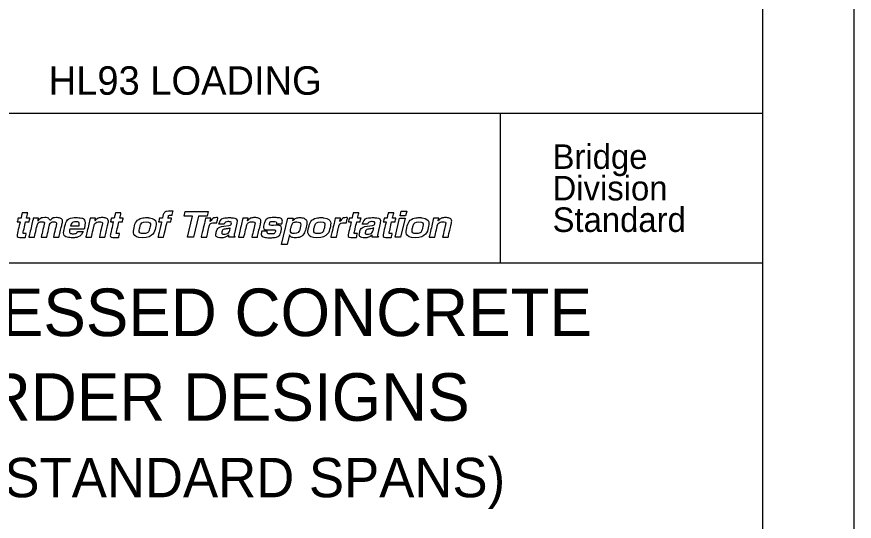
# Model space of a CAD drawing. Extents: x 998.6 to 1033.3, y 1000 to 1011.
# Drawn here: x 1014.706 to 1017, y 1001.382 to 1002.765 of the extents above; entities that cross this region are included whole.
import ezdxf

# ---------------------------------------------------------------- set-up
doc = ezdxf.new("R2010")
doc.units = 0
for name, color, linetype in [('D_BATCH_PLOT', 7, 'Continuous'), ('D_SHEET', 7, 'Continuous'), ('Working Level 1', 7, 'Continuous')]:
    doc.layers.add(name, color=color, linetype=linetype)

msp = doc.modelspace()

# ---------------------------------------------------------------- linework, layer by layer
at = {"layer": 'D_BATCH_PLOT'}
msp.add_lwpolyline([(1000, 1000), (1017, 1000), (1017, 1011), (1000, 1011)], close=True, dxfattribs=at)
at = {"layer": 'D_SHEET'}
for p, q in [((1017, 1000), (1017, 1011)), ((1016.75, 1000.25), (1016.75, 1010.75)), ((1013.725, 1002.5), (1016.75, 1002.5)), ((1016.0306, 1002.09), (1016.0306, 1002.5)), ((1015.1642, 1002.2186), (1015.1672, 1002.2311)), ((1015.1672, 1002.2311), (1015.2304, 1002.2311)), ((1015.2304, 1002.2311), (1015.2274, 1002.2186)), ((1015.756, 1002.219), (1015.759, 1002.2317)), ((1015.759, 1002.2317), (1015.7742, 1002.2317)), ((1015.7742, 1002.2317), (1015.7712, 1002.219)), ((1015.1877, 1002.2186), (1015.1642, 1002.2186)), ((1015.1741, 1002.1604), (1015.1877, 1002.2186)), ((1015.204, 1002.2186), (1015.1904, 1002.1604)), ((1015.2274, 1002.2186), (1015.204, 1002.2186)), ((1015.3088, 1002.199), (1015.3021, 1002.1707)), ((1015.7018, 1002.199), (1015.6952, 1002.1707)), ((1015.7424, 1002.1604), (1015.7546, 1002.2128)), ((1015.7546, 1002.2128), (1015.7697, 1002.2128)), ((1015.7712, 1002.219), (1015.756, 1002.219)), ((1015.7697, 1002.2128), (1015.7575, 1002.1604)), ((1014.8536, 1002.1918), (1014.8771, 1002.1918)), ((1014.8727, 1002.1758), (1014.8883, 1002.1758)), ((1015.2739, 1002.1958), (1015.2593, 1002.1958)), ((1015.2731, 1002.191), (1015.2872, 1002.1929)), ((1015.2893, 1002.1792), (1015.2909, 1002.1859)), ((1015.667, 1002.1958), (1015.6524, 1002.1958)), ((1015.6662, 1002.191), (1015.6803, 1002.1929)), ((1015.6824, 1002.1792), (1015.6839, 1002.1859)), ((1015.1904, 1002.1604), (1015.1741, 1002.1604)), ((1015.7575, 1002.1604), (1015.7424, 1002.1604)), ((1013.725, 1002.09), (1016.75, 1002.09))]:
    msp.add_line(p, q, dxfattribs=at)
for points in [[(1015.4533, 1002.1671), (1015.4531, 1002.1671), (1015.4468, 1002.1401), (1015.4316, 1002.1401), (1015.4486, 1002.2128), (1015.4631, 1002.2128), (1015.4614, 1002.2052), (1015.4616, 1002.2052)], [(1014.8912, 1002.1853), (1014.8906, 1002.1829), (1014.8511, 1002.1829)], [(1015.3036, 1002.1625), (1015.3031, 1002.1604), (1015.2868, 1002.1604)], [(1015.6966, 1002.1625), (1015.6962, 1002.1604), (1015.6798, 1002.1604)]]:
    msp.add_lwpolyline(points, dxfattribs=at)
for points, degree in [([(1014.7327, 1002.2128), (1014.7327, 1002.2128), (1014.7421, 1002.2128), (1014.7421, 1002.2128), (1014.7421, 1002.2128), (1014.7398, 1002.2029), (1014.7398, 1002.2029), (1014.7398, 1002.2029), (1014.7304, 1002.2029), (1014.7304, 1002.2029), (1014.7304, 1002.2029), (1014.7238, 1002.1745), (1014.7238, 1002.1745), (1014.7231, 1002.1714), (1014.7229, 1002.1703), (1014.7291, 1002.1703), (1014.73, 1002.1703), (1014.7312, 1002.1704), (1014.7323, 1002.1705), (1014.7323, 1002.1705), (1014.7298, 1002.16), (1014.7298, 1002.16), (1014.7274, 1002.1599), (1014.725, 1002.1598), (1014.7226, 1002.1598), (1014.7226, 1002.1598), (1014.7207, 1002.1598), (1014.7207, 1002.1598), (1014.7076, 1002.1598), (1014.7063, 1002.1644), (1014.7079, 1002.1712), (1014.7079, 1002.1712), (1014.7153, 1002.2029), (1014.7153, 1002.2029), (1014.7153, 1002.2029), (1014.7075, 1002.2029), (1014.7075, 1002.2029), (1014.7075, 1002.2029), (1014.7098, 1002.2128), (1014.7098, 1002.2128), (1014.7098, 1002.2128), (1014.7176, 1002.2128), (1014.7176, 1002.2128), (1014.7176, 1002.2128), (1014.7209, 1002.2269), (1014.7209, 1002.2269), (1014.7209, 1002.2269), (1014.736, 1002.2269), (1014.736, 1002.2269), (1014.736, 1002.2269), (1014.7327, 1002.2128), (1014.7327, 1002.2128)], 3), ([(1014.9882, 1002.2128), (1014.9882, 1002.2128), (1014.9976, 1002.2128), (1014.9976, 1002.2128), (1014.9976, 1002.2128), (1014.9953, 1002.2029), (1014.9953, 1002.2029), (1014.9953, 1002.2029), (1014.9859, 1002.2029), (1014.9859, 1002.2029), (1014.9859, 1002.2029), (1014.9792, 1002.1745), (1014.9792, 1002.1745), (1014.9785, 1002.1714), (1014.9783, 1002.1703), (1014.9845, 1002.1703), (1014.9855, 1002.1703), (1014.9866, 1002.1704), (1014.9877, 1002.1705), (1014.9877, 1002.1705), (1014.9853, 1002.16), (1014.9853, 1002.16), (1014.9829, 1002.1599), (1014.9804, 1002.1598), (1014.9781, 1002.1598), (1014.9781, 1002.1598), (1014.9761, 1002.1598), (1014.9761, 1002.1598), (1014.963, 1002.1598), (1014.9617, 1002.1644), (1014.9633, 1002.1712), (1014.9633, 1002.1712), (1014.9707, 1002.2029), (1014.9707, 1002.2029), (1014.9707, 1002.2029), (1014.9629, 1002.2029), (1014.9629, 1002.2029), (1014.9629, 1002.2029), (1014.9652, 1002.2128), (1014.9652, 1002.2128), (1014.9652, 1002.2128), (1014.973, 1002.2128), (1014.973, 1002.2128), (1014.973, 1002.2128), (1014.9763, 1002.2269), (1014.9763, 1002.2269), (1014.9763, 1002.2269), (1014.9915, 1002.2269), (1014.9915, 1002.2269), (1014.9915, 1002.2269), (1014.9882, 1002.2128), (1014.9882, 1002.2128)], 3), ([(1015.108, 1002.1604), (1015.108, 1002.1604), (1015.0929, 1002.1604), (1015.0929, 1002.1604), (1015.0929, 1002.1604), (1015.1028, 1002.2029), (1015.1028, 1002.2029), (1015.1028, 1002.2029), (1015.0945, 1002.2029), (1015.0945, 1002.2029), (1015.0945, 1002.2029), (1015.0968, 1002.2128), (1015.0968, 1002.2128), (1015.0968, 1002.2128), (1015.1051, 1002.2128), (1015.1051, 1002.2128), (1015.1051, 1002.2128), (1015.1061, 1002.217), (1015.1061, 1002.217), (1015.1086, 1002.2278), (1015.1161, 1002.2319), (1015.1265, 1002.2319), (1015.1309, 1002.2319), (1015.1329, 1002.2318), (1015.1342, 1002.2317), (1015.1342, 1002.2317), (1015.1316, 1002.2206), (1015.1316, 1002.2206), (1015.1316, 1002.2206), (1015.1274, 1002.2206), (1015.1274, 1002.2206), (1015.1222, 1002.2206), (1015.1218, 1002.2192), (1015.1207, 1002.2148), (1015.1207, 1002.2148), (1015.1203, 1002.2128), (1015.1203, 1002.2128), (1015.1203, 1002.2128), (1015.1301, 1002.2128), (1015.1301, 1002.2128), (1015.1301, 1002.2128), (1015.1278, 1002.2029), (1015.1278, 1002.2029), (1015.1278, 1002.2029), (1015.118, 1002.2029), (1015.118, 1002.2029), (1015.118, 1002.2029), (1015.108, 1002.1604), (1015.108, 1002.1604)], 3), ([(1015.6396, 1002.2128), (1015.6396, 1002.2128), (1015.649, 1002.2128), (1015.649, 1002.2128), (1015.649, 1002.2128), (1015.6467, 1002.2029), (1015.6467, 1002.2029), (1015.6467, 1002.2029), (1015.6373, 1002.2029), (1015.6373, 1002.2029), (1015.6373, 1002.2029), (1015.6306, 1002.1745), (1015.6306, 1002.1745), (1015.6299, 1002.1714), (1015.6298, 1002.1703), (1015.6359, 1002.1703), (1015.6369, 1002.1703), (1015.638, 1002.1704), (1015.6391, 1002.1705), (1015.6391, 1002.1705), (1015.6367, 1002.16), (1015.6367, 1002.16), (1015.6343, 1002.1599), (1015.6319, 1002.1598), (1015.6295, 1002.1598), (1015.6295, 1002.1598), (1015.6275, 1002.1598), (1015.6275, 1002.1598), (1015.6144, 1002.1598), (1015.6131, 1002.1644), (1015.6147, 1002.1712), (1015.6147, 1002.1712), (1015.6221, 1002.2029), (1015.6221, 1002.2029), (1015.6221, 1002.2029), (1015.6143, 1002.2029), (1015.6143, 1002.2029), (1015.6143, 1002.2029), (1015.6166, 1002.2128), (1015.6166, 1002.2128), (1015.6166, 1002.2128), (1015.6244, 1002.2128), (1015.6244, 1002.2128), (1015.6244, 1002.2128), (1015.6277, 1002.2269), (1015.6277, 1002.2269), (1015.6277, 1002.2269), (1015.6429, 1002.2269), (1015.6429, 1002.2269), (1015.6429, 1002.2269), (1015.6396, 1002.2128), (1015.6396, 1002.2128)], 3), ([(1015.7353, 1002.2128), (1015.7353, 1002.2128), (1015.7447, 1002.2128), (1015.7447, 1002.2128), (1015.7447, 1002.2128), (1015.7424, 1002.2029), (1015.7424, 1002.2029), (1015.7424, 1002.2029), (1015.733, 1002.2029), (1015.733, 1002.2029), (1015.733, 1002.2029), (1015.7264, 1002.1745), (1015.7264, 1002.1745), (1015.7257, 1002.1714), (1015.7255, 1002.1703), (1015.7317, 1002.1703), (1015.7326, 1002.1703), (1015.7337, 1002.1704), (1015.7348, 1002.1705), (1015.7348, 1002.1705), (1015.7324, 1002.16), (1015.7324, 1002.16), (1015.73, 1002.1599), (1015.7276, 1002.1598), (1015.7252, 1002.1598), (1015.7252, 1002.1598), (1015.7233, 1002.1598), (1015.7233, 1002.1598), (1015.7102, 1002.1598), (1015.7089, 1002.1644), (1015.7105, 1002.1712), (1015.7105, 1002.1712), (1015.7179, 1002.2029), (1015.7179, 1002.2029), (1015.7179, 1002.2029), (1015.7101, 1002.2029), (1015.7101, 1002.2029), (1015.7101, 1002.2029), (1015.7124, 1002.2128), (1015.7124, 1002.2128), (1015.7124, 1002.2128), (1015.7202, 1002.2128), (1015.7202, 1002.2128), (1015.7202, 1002.2128), (1015.7235, 1002.2269), (1015.7235, 1002.2269), (1015.7235, 1002.2269), (1015.7386, 1002.2269), (1015.7386, 1002.2269), (1015.7386, 1002.2269), (1015.7353, 1002.2128), (1015.7353, 1002.2128)], 3), ([(1014.8217, 1002.1604), (1014.8217, 1002.1604), (1014.8065, 1002.1604), (1014.8065, 1002.1604), (1014.8065, 1002.1604), (1014.8139, 1002.1922), (1014.8139, 1002.1922), (1014.8158, 1002.2), (1014.8126, 1002.2025), (1014.8081, 1002.2025), (1014.8006, 1002.2025), (1014.7968, 1002.198), (1014.7953, 1002.1918), (1014.7953, 1002.1918), (1014.788, 1002.1604), (1014.788, 1002.1604), (1014.788, 1002.1604), (1014.7729, 1002.1604), (1014.7729, 1002.1604), (1014.7729, 1002.1604), (1014.7802, 1002.1919), (1014.7802, 1002.1919), (1014.7813, 1002.1963), (1014.7827, 1002.2025), (1014.7736, 1002.2025), (1014.7665, 1002.2025), (1014.7632, 1002.198), (1014.7618, 1002.1923), (1014.7618, 1002.1923), (1014.7544, 1002.1604), (1014.7544, 1002.1604), (1014.7544, 1002.1604), (1014.7392, 1002.1604), (1014.7392, 1002.1604), (1014.7392, 1002.1604), (1014.7514, 1002.2128), (1014.7514, 1002.2128), (1014.7514, 1002.2128), (1014.766, 1002.2128), (1014.766, 1002.2128), (1014.766, 1002.2128), (1014.7642, 1002.2051), (1014.7642, 1002.2051), (1014.7642, 1002.2051), (1014.7644, 1002.2051), (1014.7644, 1002.2051), (1014.7671, 1002.2085), (1014.7726, 1002.2141), (1014.7828, 1002.2141), (1014.7911, 1002.2141), (1014.7943, 1002.2114), (1014.7969, 1002.2058), (1014.7994, 1002.2083), (1014.805, 1002.2141), (1014.8142, 1002.2141), (1014.8254, 1002.2141), (1014.8328, 1002.2081), (1014.8301, 1002.1966), (1014.8301, 1002.1966), (1014.8217, 1002.1604), (1014.8217, 1002.1604)], 3), ([(1014.8883, 1002.1758), (1014.8814, 1002.1632), (1014.8689, 1002.1591), (1014.8591, 1002.1591), (1014.8429, 1002.1591), (1014.8321, 1002.1661), (1014.8371, 1002.1877), (1014.8386, 1002.194), (1014.8457, 1002.2141), (1014.8709, 1002.2141), (1014.8822, 1002.2141), (1014.8968, 1002.2092), (1014.8912, 1002.1853)], 3), ([(1014.8771, 1002.1918), (1014.8783, 1002.2003), (1014.8729, 1002.2028), (1014.868, 1002.2028), (1014.8609, 1002.2028), (1014.8561, 1002.1987), (1014.8536, 1002.1918)], 3), ([(1014.9473, 1002.1604), (1014.9473, 1002.1604), (1014.9321, 1002.1604), (1014.9321, 1002.1604), (1014.9321, 1002.1604), (1014.9395, 1002.1922), (1014.9395, 1002.1922), (1014.9404, 1002.196), (1014.9417, 1002.2025), (1014.9321, 1002.2025), (1014.9254, 1002.2025), (1014.9192, 1002.1984), (1014.9174, 1002.1904), (1014.9174, 1002.1904), (1014.9104, 1002.1604), (1014.9104, 1002.1604), (1014.9104, 1002.1604), (1014.8952, 1002.1604), (1014.8952, 1002.1604), (1014.8952, 1002.1604), (1014.9075, 1002.2128), (1014.9075, 1002.2128), (1014.9075, 1002.2128), (1014.922, 1002.2128), (1014.922, 1002.2128), (1014.922, 1002.2128), (1014.9202, 1002.2051), (1014.9202, 1002.2051), (1014.9202, 1002.2051), (1014.9204, 1002.2051), (1014.9204, 1002.2051), (1014.9232, 1002.2082), (1014.9289, 1002.2141), (1014.9398, 1002.2141), (1014.9511, 1002.2141), (1014.9584, 1002.2081), (1014.9557, 1002.1966), (1014.9557, 1002.1966), (1014.9473, 1002.1604), (1014.9473, 1002.1604)], 3), ([(1015.0504, 1002.1591), (1015.0349, 1002.1591), (1015.023, 1002.1677), (1015.0274, 1002.1866), (1015.0318, 1002.2055), (1015.0478, 1002.2141), (1015.0632, 1002.2141), (1015.0654, 1002.2141), (1015.0674, 1002.214), (1015.0694, 1002.2137)], 3), ([(1015.0605, 1002.2025), (1015.0488, 1002.2025), (1015.0445, 1002.1933), (1015.043, 1002.1866), (1015.0414, 1002.1799), (1015.0414, 1002.1707), (1015.0531, 1002.1707), (1015.0648, 1002.1707), (1015.0691, 1002.1799), (1015.0707, 1002.1866), (1015.0722, 1002.1933), (1015.0722, 1002.2025), (1015.0605, 1002.2025)], 3), ([(1015.0694, 1002.2137), (1015.0817, 1002.2116), (1015.09, 1002.2029), (1015.0862, 1002.1866), (1015.0818, 1002.1677), (1015.0658, 1002.1591), (1015.0504, 1002.1591)], 3), ([(1015.2234, 1002.2128), (1015.2234, 1002.2128), (1015.2379, 1002.2128), (1015.2379, 1002.2128), (1015.2379, 1002.2128), (1015.2357, 1002.2037), (1015.2357, 1002.2037), (1015.2357, 1002.2037), (1015.236, 1002.2037), (1015.236, 1002.2037), (1015.2403, 1002.209), (1015.245, 1002.2141), (1015.2542, 1002.2141), (1015.2552, 1002.2141), (1015.2561, 1002.214), (1015.2571, 1002.2139), (1015.2571, 1002.2139), (1015.2538, 1002.2), (1015.2538, 1002.2), (1015.2526, 1002.2002), (1015.2509, 1002.2002), (1015.2495, 1002.2002), (1015.2377, 1002.2002), (1015.234, 1002.1935), (1015.2326, 1002.1877), (1015.2326, 1002.1877), (1015.2263, 1002.1604), (1015.2263, 1002.1604), (1015.2263, 1002.1604), (1015.2111, 1002.1604), (1015.2111, 1002.1604), (1015.2111, 1002.1604), (1015.2234, 1002.2128), (1015.2234, 1002.2128)], 3), ([(1015.2593, 1002.1958), (1015.2648, 1002.2119), (1015.2776, 1002.2141), (1015.2894, 1002.2141), (1015.2975, 1002.2141), (1015.3118, 1002.2119), (1015.3088, 1002.199)], 3), ([(1015.2872, 1002.1929), (1015.2897, 1002.1932), (1015.2928, 1002.1941), (1015.2935, 1002.197), (1015.2948, 1002.2028), (1015.2888, 1002.2031), (1015.2849, 1002.2031), (1015.2774, 1002.2031), (1015.2751, 1002.1989), (1015.2739, 1002.1958)], 3), ([(1015.3651, 1002.1604), (1015.3651, 1002.1604), (1015.3499, 1002.1604), (1015.3499, 1002.1604), (1015.3499, 1002.1604), (1015.3574, 1002.1922), (1015.3574, 1002.1922), (1015.3583, 1002.196), (1015.3596, 1002.2025), (1015.3499, 1002.2025), (1015.3432, 1002.2025), (1015.3371, 1002.1984), (1015.3352, 1002.1904), (1015.3352, 1002.1904), (1015.3282, 1002.1604), (1015.3282, 1002.1604), (1015.3282, 1002.1604), (1015.3131, 1002.1604), (1015.3131, 1002.1604), (1015.3131, 1002.1604), (1015.3253, 1002.2128), (1015.3253, 1002.2128), (1015.3253, 1002.2128), (1015.3398, 1002.2128), (1015.3398, 1002.2128), (1015.3398, 1002.2128), (1015.338, 1002.2051), (1015.338, 1002.2051), (1015.338, 1002.2051), (1015.3382, 1002.2051), (1015.3382, 1002.2051), (1015.341, 1002.2082), (1015.3467, 1002.2141), (1015.3576, 1002.2141), (1015.3689, 1002.2141), (1015.3762, 1002.2081), (1015.3735, 1002.1966), (1015.3735, 1002.1966), (1015.3651, 1002.1604), (1015.3651, 1002.1604)], 3), ([(1015.4178, 1002.1968), (1015.418, 1002.2002), (1015.4175, 1002.2037), (1015.4093, 1002.2037), (1015.4011, 1002.2037), (1015.3993, 1002.2009), (1015.3988, 1002.1986), (1015.3969, 1002.1903), (1015.4343, 1002.1963), (1015.4298, 1002.1771), (1015.4262, 1002.1618), (1015.4093, 1002.1591), (1015.4004, 1002.1591), (1015.3873, 1002.1591), (1015.3741, 1002.1632), (1015.3769, 1002.1772), (1015.3769, 1002.1772), (1015.3925, 1002.1772), (1015.3925, 1002.1772), (1015.3914, 1002.1727), (1015.3937, 1002.1695), (1015.4032, 1002.1695), (1015.411, 1002.1695), (1015.4137, 1002.1729), (1015.4141, 1002.1749), (1015.4162, 1002.1836), (1015.3789, 1002.1771), (1015.3835, 1002.1966), (1015.3853, 1002.2043), (1015.3929, 1002.2141), (1015.4109, 1002.2141), (1015.4221, 1002.2141), (1015.4349, 1002.2116), (1015.4327, 1002.1968), (1015.4327, 1002.1968), (1015.4178, 1002.1968), (1015.4178, 1002.1968)], 3), ([(1015.4616, 1002.2052), (1015.4653, 1002.2093), (1015.4707, 1002.2141), (1015.4809, 1002.2141), (1015.4935, 1002.2141), (1015.5027, 1002.2053), (1015.4985, 1002.1872), (1015.4951, 1002.1728), (1015.4847, 1002.1591), (1015.4677, 1002.1591), (1015.4571, 1002.1591), (1015.4545, 1002.1643), (1015.4533, 1002.1671)], 3), ([(1015.4665, 1002.1704), (1015.4763, 1002.1704), (1015.4812, 1002.18), (1015.4827, 1002.1862), (1015.4846, 1002.1945), (1015.4832, 1002.2022), (1015.4735, 1002.2022), (1015.4631, 1002.2022), (1015.4587, 1002.1938), (1015.4567, 1002.1854), (1015.4549, 1002.1777), (1015.4569, 1002.1704), (1015.4665, 1002.1704)], 3), ([(1015.5284, 1002.1591), (1015.5129, 1002.1591), (1015.501, 1002.1677), (1015.5054, 1002.1866), (1015.5098, 1002.2055), (1015.5258, 1002.2141), (1015.5412, 1002.2141), (1015.5434, 1002.2141), (1015.5454, 1002.214), (1015.5474, 1002.2137)], 3), ([(1015.5385, 1002.2025), (1015.5268, 1002.2025), (1015.5225, 1002.1933), (1015.5209, 1002.1866), (1015.5194, 1002.1799), (1015.5194, 1002.1707), (1015.5311, 1002.1707), (1015.5427, 1002.1707), (1015.5471, 1002.1799), (1015.5486, 1002.1866), (1015.5502, 1002.1933), (1015.5502, 1002.2025), (1015.5385, 1002.2025)], 3), ([(1015.5474, 1002.2137), (1015.5597, 1002.2116), (1015.568, 1002.2029), (1015.5642, 1002.1866), (1015.5598, 1002.1677), (1015.5438, 1002.1591), (1015.5284, 1002.1591)], 3), ([(1015.5785, 1002.2128), (1015.5785, 1002.2128), (1015.5929, 1002.2128), (1015.5929, 1002.2128), (1015.5929, 1002.2128), (1015.5908, 1002.2037), (1015.5908, 1002.2037), (1015.5908, 1002.2037), (1015.5911, 1002.2037), (1015.5911, 1002.2037), (1015.5954, 1002.209), (1015.6001, 1002.2141), (1015.6093, 1002.2141), (1015.6103, 1002.2141), (1015.6112, 1002.214), (1015.6122, 1002.2139), (1015.6122, 1002.2139), (1015.6089, 1002.2), (1015.6089, 1002.2), (1015.6076, 1002.2002), (1015.606, 1002.2002), (1015.6046, 1002.2002), (1015.5928, 1002.2002), (1015.5891, 1002.1935), (1015.5877, 1002.1877), (1015.5877, 1002.1877), (1015.5814, 1002.1604), (1015.5814, 1002.1604), (1015.5814, 1002.1604), (1015.5662, 1002.1604), (1015.5662, 1002.1604), (1015.5662, 1002.1604), (1015.5785, 1002.2128), (1015.5785, 1002.2128)], 3), ([(1015.6524, 1002.1958), (1015.6579, 1002.2119), (1015.6706, 1002.2141), (1015.6824, 1002.2141), (1015.6905, 1002.2141), (1015.7048, 1002.2119), (1015.7018, 1002.199)], 3), ([(1015.6803, 1002.1929), (1015.6827, 1002.1932), (1015.6858, 1002.1941), (1015.6865, 1002.197), (1015.6879, 1002.2028), (1015.6819, 1002.2031), (1015.678, 1002.2031), (1015.6704, 1002.2031), (1015.6681, 1002.1989), (1015.667, 1002.1958)], 3), ([(1015.7975, 1002.1591), (1015.7821, 1002.1591), (1015.7701, 1002.1677), (1015.7745, 1002.1866), (1015.779, 1002.2055), (1015.7949, 1002.2141), (1015.8104, 1002.2141), (1015.8125, 1002.2141), (1015.8146, 1002.214), (1015.8165, 1002.2137)], 3), ([(1015.8077, 1002.2025), (1015.796, 1002.2025), (1015.7917, 1002.1933), (1015.7901, 1002.1866), (1015.7886, 1002.1799), (1015.7886, 1002.1707), (1015.8002, 1002.1707), (1015.8119, 1002.1707), (1015.8163, 1002.1799), (1015.8178, 1002.1866), (1015.8194, 1002.1933), (1015.8194, 1002.2025), (1015.8077, 1002.2025)], 3), ([(1015.8165, 1002.2137), (1015.8288, 1002.2116), (1015.8372, 1002.2029), (1015.8334, 1002.1866), (1015.829, 1002.1677), (1015.813, 1002.1591), (1015.7975, 1002.1591)], 3), ([(1015.8875, 1002.1604), (1015.8875, 1002.1604), (1015.8724, 1002.1604), (1015.8724, 1002.1604), (1015.8724, 1002.1604), (1015.8798, 1002.1922), (1015.8798, 1002.1922), (1015.8807, 1002.196), (1015.882, 1002.2025), (1015.8724, 1002.2025), (1015.8657, 1002.2025), (1015.8595, 1002.1984), (1015.8577, 1002.1904), (1015.8577, 1002.1904), (1015.8507, 1002.1604), (1015.8507, 1002.1604), (1015.8507, 1002.1604), (1015.8355, 1002.1604), (1015.8355, 1002.1604), (1015.8355, 1002.1604), (1015.8477, 1002.2128), (1015.8477, 1002.2128), (1015.8477, 1002.2128), (1015.8622, 1002.2128), (1015.8622, 1002.2128), (1015.8622, 1002.2128), (1015.8604, 1002.2051), (1015.8604, 1002.2051), (1015.8604, 1002.2051), (1015.8607, 1002.2051), (1015.8607, 1002.2051), (1015.8634, 1002.2082), (1015.8692, 1002.2141), (1015.8801, 1002.2141), (1015.8913, 1002.2141), (1015.8987, 1002.2081), (1015.896, 1002.1966), (1015.896, 1002.1966), (1015.8875, 1002.1604), (1015.8875, 1002.1604)], 3), ([(1014.8511, 1002.1829), (1014.8506, 1002.1789), (1014.8494, 1002.1701), (1014.8617, 1002.1701), (1014.8659, 1002.1701), (1014.8707, 1002.172), (1014.8727, 1002.1758)], 3), ([(1015.2868, 1002.1666), (1015.2826, 1002.1634), (1015.2767, 1002.1591), (1015.2664, 1002.1591), (1015.2578, 1002.1591), (1015.2499, 1002.1635), (1015.2525, 1002.1743), (1015.2549, 1002.1845), (1015.2632, 1002.1897), (1015.2731, 1002.191)], 3), ([(1015.2909, 1002.1859), (1015.2891, 1002.1848), (1015.2864, 1002.1839), (1015.2799, 1002.1831), (1015.2741, 1002.1822), (1015.2691, 1002.1809), (1015.2678, 1002.1752), (1015.2667, 1002.1704), (1015.2705, 1002.1689), (1015.2734, 1002.1689), (1015.2801, 1002.1689), (1015.2878, 1002.1728), (1015.2893, 1002.1792)], 3), ([(1015.6799, 1002.1666), (1015.6756, 1002.1634), (1015.6698, 1002.1591), (1015.6595, 1002.1591), (1015.6508, 1002.1591), (1015.643, 1002.1635), (1015.6455, 1002.1743), (1015.6479, 1002.1845), (1015.6563, 1002.1897), (1015.6662, 1002.191)], 3), ([(1015.6839, 1002.1859), (1015.6822, 1002.1848), (1015.6795, 1002.1839), (1015.673, 1002.1831), (1015.6672, 1002.1822), (1015.6622, 1002.1809), (1015.6609, 1002.1752), (1015.6597, 1002.1704), (1015.6635, 1002.1689), (1015.6664, 1002.1689), (1015.6731, 1002.1689), (1015.6809, 1002.1728), (1015.6824, 1002.1792)], 3), ([(1015.2868, 1002.1604), (1015.2865, 1002.1629), (1015.2864, 1002.1637), (1015.2868, 1002.1666)], 2), ([(1015.3021, 1002.1707), (1015.3007, 1002.1645), (1015.3019, 1002.1631), (1015.3036, 1002.1625)], 2), ([(1015.6798, 1002.1604), (1015.6795, 1002.1629), (1015.6795, 1002.1637), (1015.6799, 1002.1666)], 2), ([(1015.6952, 1002.1707), (1015.6937, 1002.1645), (1015.6949, 1002.1631), (1015.6966, 1002.1625)], 2)]:
    msp.add_open_spline(points, degree=degree, dxfattribs=at)

# ---------------------------------------------------------------- texts
for s, p in [('Bridge', (1016.1737, 1002.3477)), ('Division', (1016.1737, 1002.2613)), ('Standard', (1016.1737, 1002.1749))]:
    msp.add_text(s, height=0.06725, dxfattribs=at).set_placement(p)
at = {"layer": 'Working Level 1'}
for s, height, p in [('HL93 LOADING', 0.077999, (1014.7935, 1002.5508)), ('PRESTRESSED CONCRETE', 0.130498, (1013.9546, 1001.8894)), ('I-GIRDER DESIGNS', 0.1305, (1014.3276, 1001.6574)), ('(NON-STANDARD SPANS)', 0.107956, (1014.2552, 1001.448))]:
    msp.add_text(s, height=height, dxfattribs=at).set_placement(p)

doc.saveas('drawing.dxf')
